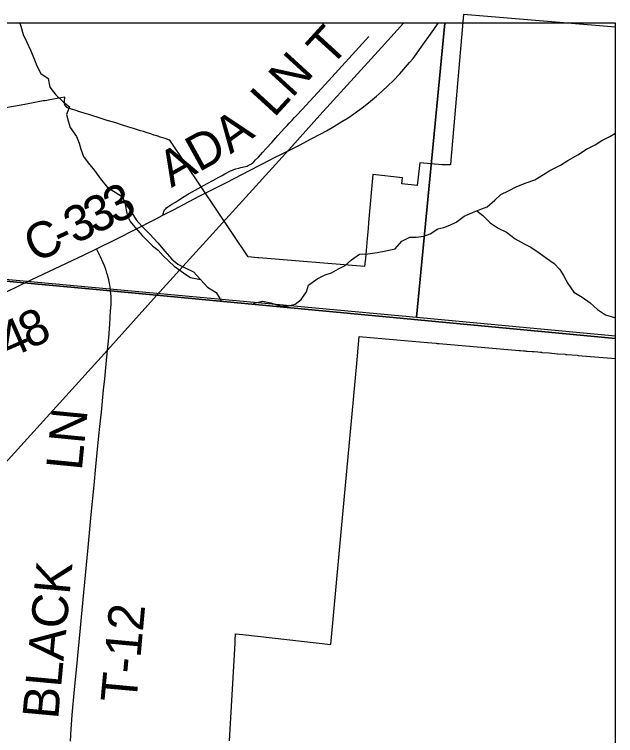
# Model space of a CAD drawing. Extents: x -1.4 to 35.4, y 0 to 22.
# Drawn here: x 30.337 to 31.29, y 18.725 to 19.869 of the extents above; entities that cross this region are included whole.
import ezdxf

# ---------------------------------------------------------------- set-up
doc = ezdxf.new("R2010")
doc.units = 0
for name, color, linetype in [('GM_X_County_Road', 7, 'Continuous'), ('GM_X_County_Road_Text', 7, 'Continuous'), ('GM_X_County_Text', 7, 'Continuous'), ('GM_X_Minor_Lake', 7, 'Continuous'), ('GM_X_Minor_River', 7, 'Continuous'), ('GM_X_Rail_Line', 7, 'Continuous'), ('GM_X_Township_Road', 7, 'Continuous'), ('GM_X_Township_Road_Text', 7, 'Continuous'), ('SC_Scratch1', 7, 'Continuous'), ('SH_Border', 7, 'Continuous'), ('SH_Cut_Line', 7, 'Continuous')]:
    doc.layers.add(name, color=color, linetype=linetype)

msp = doc.modelspace()

# ---------------------------------------------------------------- linework, layer by layer
at = {"layer": 'GM_X_County_Road'}
for points in [[(31.0192, 19.8546), (30.0509, 19.8546), (30.0137, 19.4774), (30.9744, 19.3887)], [(31.2897, 19.3589), (31.2897, 19.8546), (31.0192, 19.8546), (30.9744, 19.3887)]]:
    msp.add_lwpolyline(points, close=True, dxfattribs=at)
for points in [[(30.5727, 19.5503), (30.5892, 19.5588), (30.6141, 19.5719), (30.6309, 19.5808), (30.6562, 19.5934), (30.6743, 19.6028), (30.7096, 19.6209), (30.7437, 19.6384), (30.7496, 19.6417), (30.7607, 19.6471), (30.7754, 19.6545), (30.789, 19.6615), (30.8077, 19.6713), (30.8226, 19.6791), (30.8317, 19.6841), (30.8432, 19.6908), (30.856, 19.6986), (30.8659, 19.7048), (30.8752, 19.7111), (30.8902, 19.7218), (30.9014, 19.7308), (30.9112, 19.7389), (30.92, 19.7469), (30.9296, 19.7557), (30.9372, 19.7633), (30.9478, 19.7743), (30.9634, 19.7921), (30.9688, 19.7988), (30.9744, 19.8062), (30.9792, 19.8127), (31.0016, 19.8445), (31.0086, 19.8546)], [(30.4676, 19.4969), (30.5009, 19.5132), (30.5589, 19.5431), (30.5727, 19.5503)], [(30.3526, 19.4426), (30.3551, 19.4437), (30.4479, 19.4873), (30.4676, 19.4969)], [(30.3105, 19.4224), (30.3399, 19.4362), (30.3526, 19.4426)]]:
    msp.add_lwpolyline(points, dxfattribs=at)
at = {"layer": 'GM_X_County_Text'}
msp.add_lwpolyline([(30.6779, 18.7168), (30.6868, 18.872), (30.6871, 18.8771), (30.6877, 18.8866), (30.6991, 18.8853), (30.8384, 18.8698), (30.8555, 19.0535), (30.8745, 19.2579), (30.8803, 19.321), (30.8834, 19.3577), (30.9434, 19.3525), (30.9917, 19.3483), (31.0056, 19.3471), (31.0068, 19.347), (31.0102, 19.3467), (31.1369, 19.3359), (31.1381, 19.3358), (31.1392, 19.3357), (31.144, 19.3353), (31.1464, 19.3351), (31.1483, 19.3349), (31.1494, 19.3348), (31.1575, 19.3341), (31.1596, 19.334), (31.1608, 19.3339), (31.1664, 19.3334), (31.1709, 19.333), (31.1721, 19.3329), (31.1727, 19.3328), (31.1843, 19.3318), (31.1976, 19.3307), (31.1983, 19.3307), (31.2103, 19.3297), (31.2104, 19.3297), (31.2106, 19.3296), (31.2117, 19.3295), (31.2127, 19.3295), (31.2289, 19.3281), (31.2303, 19.328), (31.2897, 19.3229), (31.2897, 19.8483), (31.1502, 19.86), (31.0488, 19.8685), (31.0287, 19.6375), (31.028, 19.6299), (31.015, 19.6303), (30.997, 19.6318), (30.9797, 19.6333), (30.9765, 19.6065), (30.9754, 19.5971), (30.9509, 19.6), (30.952, 19.6094), (30.9053, 19.6149), (30.8985, 19.5389), (30.8976, 19.5294), (30.8961, 19.5134), (30.8944, 19.4944), (30.8938, 19.4879), (30.8933, 19.482), (30.8921, 19.4687), (30.7243, 19.4826), (30.7227, 19.4828), (30.7075, 19.484), (30.5835, 19.6693), (30.5833, 19.6694), (30.5831, 19.6694), (30.576, 19.6718), (30.5724, 19.6729), (30.5685, 19.6741), (30.5681, 19.6742), (30.5661, 19.6749), (30.5631, 19.6758), (30.5631, 19.6758), (30.5607, 19.6766), (30.5587, 19.6772), (30.5584, 19.6773), (30.5533, 19.6791), (30.5474, 19.681), (30.5418, 19.6827), (30.5417, 19.6827), (30.537, 19.6842), (30.5369, 19.6842), (30.5324, 19.6857), (30.5262, 19.6876), (30.526, 19.6876), (30.5188, 19.69), (30.507, 19.6937), (30.498, 19.6965), (30.4862, 19.7001), (30.4861, 19.7001), (30.4763, 19.7031), (30.4762, 19.7031), (30.4683, 19.7056), (30.4631, 19.7073), (30.46, 19.7082), (30.4599, 19.7082), (30.4598, 19.7082), (30.4552, 19.7097), (30.448, 19.712), (30.4426, 19.7137), (30.4371, 19.7154), (30.437, 19.7155), (30.4291, 19.718), (30.4232, 19.7198), (30.423, 19.7198), (30.4227, 19.7199), (30.4226, 19.72), (30.4225, 19.72), (30.4222, 19.7201), (30.422, 19.7202), (30.4218, 19.7203), (30.4217, 19.7204), (30.4215, 19.7205), (30.4212, 19.7206), (30.4211, 19.7207), (30.421, 19.7208), (30.4208, 19.7209), (30.4206, 19.7211), (30.4204, 19.7212), (30.4203, 19.7213), (30.4201, 19.7214), (30.4199, 19.7216), (30.4198, 19.7217), (30.4197, 19.7218), (30.4195, 19.722), (30.4193, 19.7221), (30.4192, 19.7222), (30.4191, 19.7224), (30.4189, 19.7225), (30.4187, 19.7227), (30.4186, 19.7229), (30.4185, 19.723), (30.4184, 19.7232), (30.4182, 19.7234), (30.4181, 19.7235), (30.4181, 19.7237), (30.4179, 19.7239), (30.4178, 19.7241), (30.4177, 19.7242), (30.4176, 19.7244), (30.4175, 19.7246), (30.4174, 19.7248), (30.4173, 19.725), (30.4173, 19.7251), (30.4172, 19.7254), (30.4171, 19.7256), (30.417, 19.7257), (30.417, 19.7259), (30.4169, 19.7261), (30.4168, 19.7264), (30.4168, 19.7265), (30.4168, 19.7267), (30.4167, 19.7269), (30.4167, 19.7272), (30.4166, 19.7273), (30.4166, 19.7275), (30.4166, 19.7277), (30.4166, 19.728), (30.4166, 19.7282), (30.4165, 19.7283), (30.4165, 19.7286), (30.4165, 19.7288), (30.4165, 19.729), (30.4165, 19.7291), (30.4166, 19.7294), (30.4166, 19.7297), (30.4168, 19.7318), (30.417, 19.7366), (30.4169, 19.7374), (30.3935, 19.7332), (30.3858, 19.7318), (30.3828, 19.7313), (30.3538, 19.726), (30.3149, 19.7189)], dxfattribs=at)
at = {"layer": 'GM_X_Minor_Lake'}
for points in [[(30.5125, 19.57), (30.5161, 19.551), (30.5205, 19.5404), (30.5253, 19.5343), (30.5328, 19.5262), (30.5399, 19.5178), (30.5563, 19.5017), (30.5649, 19.4947), (30.5731, 19.4859), (30.5821, 19.4775), (30.5903, 19.4694), (30.5993, 19.4629), (30.6075, 19.4575), (30.6165, 19.4517), (30.632, 19.4485)], [(30.5125, 19.57), (30.5218, 19.5567), (30.53, 19.5429), (30.5393, 19.5329), (30.552, 19.5199), (30.5647, 19.5065), (30.5758, 19.4931), (30.5866, 19.4805), (30.5964, 19.4728), (30.6088, 19.4662), (30.6212, 19.4603), (30.632, 19.4485)]]:
    msp.add_lwpolyline(points, dxfattribs=at)
at = {"layer": 'GM_X_Minor_River'}
for points in [[(30.346, 19.8546), (30.3474, 19.8498), (30.3514, 19.8368), (30.3566, 19.8258), (30.3636, 19.8106), (30.3694, 19.7968), (30.3731, 19.7873), (30.379, 19.7751), (30.3906, 19.767), (30.3935, 19.7534), (30.4028, 19.7411), (30.4144, 19.73), (30.4245, 19.7219), (30.4201, 19.7098), (30.4227, 19.6996), (30.4259, 19.6893), (30.4356, 19.6748), (30.44, 19.6645), (30.4425, 19.655), (30.4469, 19.6432), (30.454, 19.6333), (30.464, 19.621), (30.4737, 19.608), (30.4849, 19.5942), (30.4969, 19.5865), (30.5085, 19.5795), (30.5125, 19.57), (30.5218, 19.5567), (30.53, 19.5429), (30.5393, 19.5329), (30.552, 19.5199), (30.5647, 19.5065), (30.5758, 19.4931), (30.5866, 19.4805), (30.5964, 19.4728), (30.6088, 19.4662), (30.6212, 19.4603), (30.632, 19.4485), (30.6432, 19.4362), (30.657, 19.4277), (30.6626, 19.4181), (30.6656, 19.4134)], [(31.0178, 19.5309), (31.0273, 19.5346), (31.0372, 19.539), (31.0497, 19.5487), (31.063, 19.5546), (31.0737, 19.5586), (31.0862, 19.5634), (31.0984, 19.5742), (31.108, 19.5828), (31.1198, 19.5891), (31.1335, 19.5958), (31.1479, 19.6013), (31.1616, 19.6064), (31.1757, 19.615), (31.1856, 19.6209), (31.2023, 19.6298), (31.2141, 19.6369), (31.2297, 19.6461), (31.2434, 19.6551), (31.2571, 19.6617), (31.2678, 19.6688), (31.2807, 19.6751), (31.2897, 19.6803)], [(31.0701, 19.5573), (31.0792, 19.5498), (31.0912, 19.5383), (31.1036, 19.5298), (31.1167, 19.5232), (31.1306, 19.5128), (31.1448, 19.5051), (31.1553, 19.4997), (31.1685, 19.4908), (31.1805, 19.4819), (31.1924, 19.4738), (31.2014, 19.4642), (31.207, 19.4547), (31.214, 19.4417), (31.2236, 19.428), (31.2368, 19.4202), (31.2495, 19.4114), (31.2611, 19.4006), (31.2738, 19.3921), (31.2881, 19.3878), (31.2897, 19.3876)], [(30.7143, 19.4088), (30.7173, 19.411), (30.7306, 19.4139), (30.7438, 19.4111), (30.7577, 19.4068), (30.7694, 19.4059), (30.7819, 19.4091), (30.7918, 19.4166), (30.7999, 19.4286), (30.8031, 19.4395), (30.8172, 19.4496), (30.8298, 19.4559), (30.8396, 19.4588), (30.8507, 19.4651), (30.8613, 19.4707), (30.8716, 19.4796), (30.8838, 19.4882), (30.8971, 19.4892), (30.9122, 19.4909), (30.9255, 19.4938), (30.9406, 19.497), (30.951, 19.509), (30.9639, 19.5156), (30.9737, 19.5155), (30.9858, 19.5169), (30.9961, 19.5209), (31.0083, 19.5284), (31.0178, 19.5309)]]:
    msp.add_lwpolyline(points, dxfattribs=at)
at = {"layer": 'GM_X_Rail_Line'}
for points in [[(30.5626, 19.4228), (30.7615, 19.6421), (30.777, 19.6593), (30.8214, 19.7087), (30.9191, 19.8163), (30.9536, 19.8546)], [(27.6809, 16.2406), (27.8773, 16.4568), (28.0666, 16.6664), (28.2565, 16.8767), (28.5102, 17.1567), (28.7824, 17.456), (28.9519, 17.6445), (29.0644, 17.7684), (29.1389, 17.8512), (29.2555, 17.9795), (29.395, 18.1338), (29.7728, 18.5512), (29.9357, 18.7301), (30.4846, 19.3365), (30.5626, 19.4228)]]:
    msp.add_lwpolyline(points, dxfattribs=at)
at = {"layer": 'GM_X_Township_Road'}
for points in [[(30.7366, 19.6565), (30.745, 19.6657), (30.7547, 19.6764), (30.7599, 19.6823), (30.7651, 19.6881), (30.7694, 19.6927), (30.7728, 19.6963), (30.7775, 19.701), (30.7813, 19.705), (30.7837, 19.7077), (30.7931, 19.7178), (30.8298, 19.7573), (30.8986, 19.8338)], [(30.5727, 19.5503), (30.573, 19.5522), (30.5734, 19.554), (30.574, 19.5559), (30.5746, 19.5573), (30.5753, 19.5587), (30.5761, 19.5596), (30.577, 19.5605), (30.5784, 19.5619), (30.5803, 19.5635), (30.5834, 19.5657), (30.5868, 19.5678), (30.5923, 19.5711), (30.5974, 19.5743), (30.6064, 19.5801), (30.6131, 19.5841), (30.6189, 19.5874), (30.6285, 19.5928), (30.6379, 19.5977), (30.6438, 19.601), (30.6517, 19.6054), (30.661, 19.6105), (30.6664, 19.6134), (30.6705, 19.6157), (30.6741, 19.6175), (30.6775, 19.6193), (30.6796, 19.6204), (30.6826, 19.6218), (30.6851, 19.6228), (30.6883, 19.6239), (30.6926, 19.6249), (30.6961, 19.6257), (30.6988, 19.6263), (30.7009, 19.6267), (30.7035, 19.6275), (30.7059, 19.6282), (30.7078, 19.629), (30.7096, 19.6299), (30.7127, 19.6318), (30.7148, 19.6333), (30.7164, 19.6348), (30.7195, 19.6378), (30.7238, 19.6422), (30.7306, 19.6498), (30.736, 19.6558), (30.7366, 19.6565)], [(30.4898, 19.4297), (30.4889, 19.4361), (30.4878, 19.4423), (30.4868, 19.4478), (30.486, 19.4513), (30.4852, 19.4543), (30.4839, 19.4583), (30.4825, 19.4623), (30.4814, 19.4655), (30.4799, 19.4698), (30.478, 19.4747), (30.476, 19.4797), (30.4738, 19.4844), (30.4676, 19.4969)], [(30.4268, 18.7276), (30.429, 18.7579), (30.4325, 18.7981), (30.4361, 18.8346), (30.4388, 18.863), (30.4409, 18.8847), (30.4473, 18.9521), (30.4541, 19.0232), (30.4591, 19.0758), (30.4639, 19.1221), (30.4663, 19.1519), (30.4689, 19.1791), (30.4701, 19.1895), (30.4713, 19.2007), (30.4727, 19.2155), (30.4751, 19.2377), (30.4787, 19.2736), (30.4804, 19.2909), (30.4832, 19.3199), (30.4847, 19.336), (30.4858, 19.3458), (30.4867, 19.3557), (30.4885, 19.3776), (30.4892, 19.3882), (30.4898, 19.3986), (30.4904, 19.4087), (30.4907, 19.4158), (30.4906, 19.4217), (30.4898, 19.4297)], [(30.4262, 18.7164), (30.4264, 18.7188), (30.4267, 18.7238), (30.4267, 18.7266), (30.4268, 18.7276)]]:
    msp.add_lwpolyline(points, dxfattribs=at)
at = {"layer": 'SC_Scratch1'}
msp.add_lwpolyline([(31.2897, 19.3549), (31.2897, 19.8546), (28.0984, 19.8546), (28.0892, 19.8299), (28.0758, 19.815), (28.0371, 19.7956), (28.0133, 19.7703), (27.9969, 19.745), (27.9641, 19.7122), (27.899, 19.7049), (27.8743, 19.6888), (27.8563, 19.686), (28.5343, 19.6148), (29.9993, 19.4765), (30.102, 19.4669), (30.1169, 19.4654), (30.1374, 19.4634), (30.1484, 19.4624), (30.3524, 19.4431), (30.4896, 19.4302)], close=True, dxfattribs=at)
msp.add_lwpolyline([(31.2897, 14.2945), (31.2897, 19.3549), (30.4896, 19.4302), (30.3524, 19.4431), (30.1484, 19.4624), (30.1374, 19.4634), (30.1169, 19.4654), (30.102, 19.4669), (29.9993, 19.4765), (28.5343, 19.6148), (27.8563, 19.686), (26.941, 19.7745), (26.8946, 19.2751), (26.8479, 18.8389), (26.8414, 18.7785), (26.7816, 18.7845)], dxfattribs=at)
at = {"layer": 'SH_Border'}
msp.add_lwpolyline([(24.4897, 19.8546), (24.4921, 13.0546), (31.2897, 13.0546), (31.2897, 19.8546)], close=True, dxfattribs=at)
at = {"layer": 'SH_Cut_Line'}
msp.add_lwpolyline([(31.2897, 19.3549), (31.2897, 19.8546), (26.9481, 19.8546), (26.941, 19.7745), (27.8563, 19.686), (28.5343, 19.6148), (29.9993, 19.4765), (30.102, 19.4669), (30.1169, 19.4654), (30.1374, 19.4634), (30.1484, 19.4624), (30.3524, 19.4431), (30.4896, 19.4302)], close=True, dxfattribs=at)
msp.add_lwpolyline([(31.2897, 13.0546), (31.2897, 19.3549), (30.4896, 19.4302), (30.3524, 19.4431), (30.1484, 19.4624), (30.1374, 19.4634), (30.1169, 19.4654), (30.102, 19.4669), (29.9993, 19.4765), (28.5343, 19.6148), (27.8563, 19.686), (26.941, 19.7745), (26.8946, 19.2751), (26.8479, 18.8389), (26.8414, 18.7785), (26.7816, 18.7845)], dxfattribs=at)

# ---------------------------------------------------------------- texts
at = {"layer": 'GM_X_County_Road_Text'}
for s, rotation, p in [('3', 27.1993, (30.4967, 19.5351)), ('3', 26.3521, (30.4648, 19.5193)), ('3', 25.8184, (30.433, 19.5039)), ('C', 25.1884, (30.3696, 19.474)), ('-', 25.2977, (30.4116, 19.4938)), ('8', 25.9921, (30.3615, 19.3371)), ('4', 23.6689, (30.3272, 19.322))]:
    msp.add_text(s, height=0.0568, rotation=rotation, dxfattribs=at).set_placement(p)
at = {"layer": 'GM_X_Township_Road_Text'}
for s, height, rotation, p in [('T', 0.0568, 47.6962, (30.8381, 19.7832)), ('LN', 0.05682, 47.5276, (30.7486, 19.7037)), ('A', 0.0568, 36.1084, (30.6797, 19.6463)), ('D', 0.0568, 28.9083, (30.6293, 19.6179)), ('A', 0.0568, 29.6064, (30.586, 19.5933)), ('LN', 0.05682, 84.3886, (30.444, 19.1443)), ('BLACK', 0.05682, 84.7318, (30.4065, 18.7501)), ('T-12', 0.05682, 84.7828, (30.5304, 18.7759))]:
    msp.add_text(s, height=height, rotation=rotation, dxfattribs=at).set_placement(p)

doc.saveas('drawing.dxf')
